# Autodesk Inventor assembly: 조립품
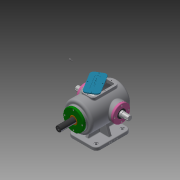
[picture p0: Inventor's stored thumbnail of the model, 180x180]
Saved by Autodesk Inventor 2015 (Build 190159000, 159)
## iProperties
Created: 2021-11
Part Number: 조립품
Document SubType Name: Assembly
Designer: G01
Author: G01
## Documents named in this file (14)
- C:\Users\G01\Desktop\711106V1010\조립품.iam
- C:\Users\G01\Desktop\711106V1010\베어링 6205.ipt
- 베어링 6205.ipt
- C:\Users\G01\Desktop\711106V1010\본체.ipt
- C:\Users\G01\Desktop\711106V1010\볼트 M4x0.7.ipt
- C:\Users\G01\Desktop\711106V1010\부시.ipt
- C:\Users\G01\Desktop\711106V1010\상부커버.ipt
- C:\Users\G01\Desktop\711106V1010\슬라이드 커버.ipt
- C:\Users\G01\Desktop\711106V1010\슬라이드.ipt
- C:\Users\G01\Desktop\711106V1010\오일실.ipt
- 오일실.ipt
- C:\Users\G01\Desktop\711106V1010\육각머리볼트 M4.ipt
- C:\Users\G01\Desktop\711106V1010\축 커버.ipt
- C:\Users\G01\Desktop\711106V1010\편심축.ipt
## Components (12 placed, 1 different names)
1. M4x0.7:1
2. M4x0.7:2
3. M4x0.7:3
4. M4x0.7:4
5. M4x0.7:5
6. M4x0.7:6
7. M4x0.7:7
8. M4x0.7:8
9. M4x0.7:9
10. M4x0.7:10
11. M4x0.7:11
12. M4x0.7:12
